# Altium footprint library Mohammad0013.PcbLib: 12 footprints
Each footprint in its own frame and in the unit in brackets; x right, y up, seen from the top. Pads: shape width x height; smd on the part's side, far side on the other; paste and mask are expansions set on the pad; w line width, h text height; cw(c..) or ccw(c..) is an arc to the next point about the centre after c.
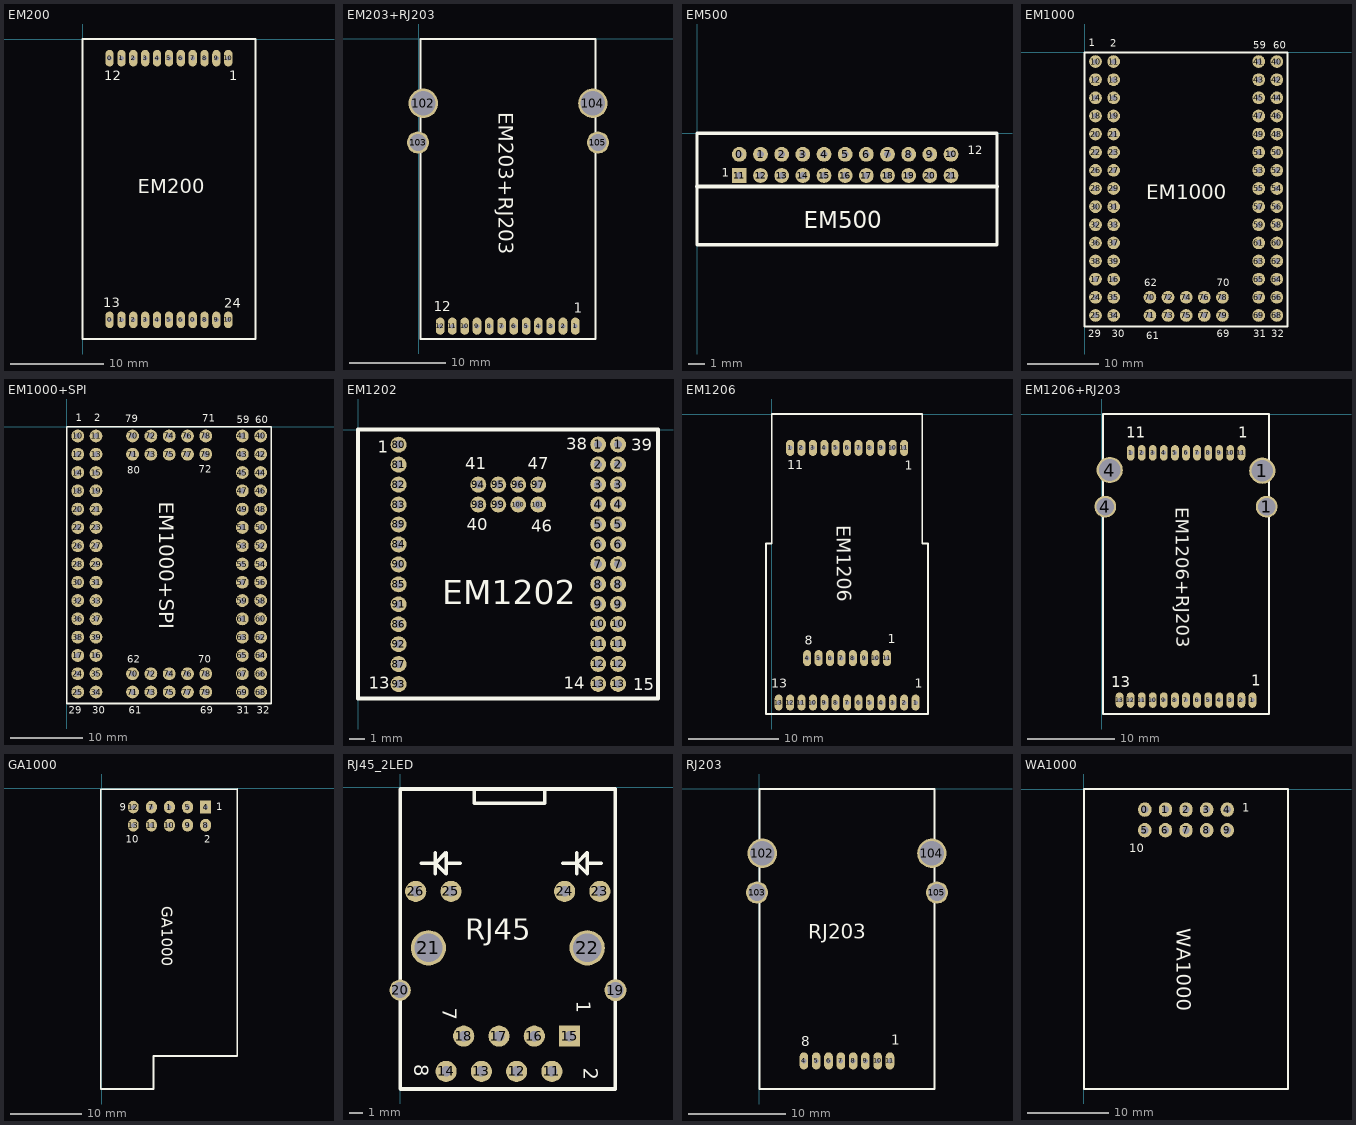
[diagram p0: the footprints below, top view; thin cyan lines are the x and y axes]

## EM200 [mil]
pads (22):
  oval 35x70 hole 20: 0(113.78,-1183.07) 0(113.78,-80.71) 0(463.78,-1183.07) 1(163.78,-1183.07) 1(163.78,-80.71) 2(213.78,-1183.07) 2(213.78,-80.71) 3(263.78,-1183.07) 3(263.78,-80.71) 4(313.78,-1183.07) 4(313.78,-80.71) 5(363.78,-1183.07) 5(363.78,-80.71) 6(413.78,-1183.07) 6(413.78,-80.71) 7(463.78,-80.71) 8(513.78,-1183.07) 8(513.78,-80.71) 9(563.78,-1183.07) 9(563.78,-80.71) 10(613.78,-1183.07) 10(613.78,-80.71)
Top Overlay:
  lines w10: 0,-1263.78 0,0 728.35,0 728.35,-1263.78 0,-1263.78
  text "24" at 596.46,-1132.87 h40
  text "13" at 86.61,-1129.92 h40
  text "1" at 618.11,-173.23 h40
  text "12" at 91.54,-173.23 h40
  text "EM200" at 232.28,-650.59 h60

## EM203+RJ203 [mm]
pads (16):
  oval 0.889x1.778 hole 0.5: 1(16.155,-29.725) 2(14.885,-29.725) 3(13.615,-29.725) 4(12.345,-29.725) 5(11.075,-29.725) 6(9.805,-29.725) 7(8.535,-29.725) 8(7.265,-29.725) 9(5.995,-29.725) 10(4.725,-29.725) 11(3.455,-29.725) 12(2.185,-29.725)
  round 3.048 hole 2.54: 102(0.45,-6.7) 104(17.975,-6.7)
  round 2.286 hole 1.778: 103(-0.1,-10.75) 105(18.5,-10.75)
Top Overlay:
  lines w0.203: 0.15,-31.05 0.15,-0.05 18.25,-0.05 18.25,-31.05 0.15,-31.05
  text "EM203+RJ203" at 8.225,-7.625 h1.52
  text "1" at 16,-28.325 h1.02
  text "12" at 1.525,-28.2 h1.02

## EM500 [mil]
pads (22):
  round 35 hole 16: 0(100,-50) 1(150,-50) 2(200,-50) 3(250,-50) 4(300,-50) 5(350,-50) 6(400,-50) 7(450,-50) 8(500,-50) 9(550,-50) 10(600,-50) 12(150,-100) 13(200,-100) 14(250,-100) 15(300,-100) 16(350,-100) 17(400,-100) 18(450,-100) 19(500,-100) 20(550,-100) 21(600,-100)
  rect 35x35 hole 16: 11(100,-100)
Top Overlay:
  lines w8: 0,-263.78 0,0 708.66,0 708.66,-263.78 0,-263.78
  lines w10: 0,-125.98 708.66,-125.98
  text "12" at 640,-50 h20
  text "1" at 59.06,-102.36 h20
  text "EM500" at 251.97,-224.41 h40

## EM1000 [mil]
pads (70):
  round 70 hole 30: 10(60,-50) 11(160,-50) 12(60,-150) 13(160,-150) 14(60,-250) 15(160,-250) 16(160,-1250) 17(60,-1250) 18(60,-350) 19(160,-350) 20(60,-450) 21(160,-450) 22(60,-550) 23(160,-550) 24(60,-1350) 25(60,-1450) 26(60,-650) 27(160,-650) 28(60,-750) 29(160,-750) 30(60,-850) 31(160,-850) 32(60,-950) 33(160,-950) 34(160,-1450) 35(160,-1350) 36(60,-1050) 37(160,-1050) 38(60,-1150) 39(160,-1150) 40(1060,-50) 41(960,-50) 42(1060,-150) 43(960,-150) 44(1060,-250) 45(960,-250) 46(1060,-350) 47(960,-350) 48(1060,-450) 49(960,-450) 50(1060,-550) 51(960,-550) 52(1060,-650) 53(960,-650) 54(1060,-750) 55(960,-750) 56(1060,-850) 57(960,-850) 58(1060,-950) 59(960,-950) 60(1060,-1050) 61(960,-1050) 62(1060,-1150) 63(960,-1150) 64(1060,-1250) 65(960,-1250) 66(1060,-1350) 67(960,-1350) 68(1060,-1450) 69(960,-1450) 70(360,-1350) 71(360,-1450) 72(460,-1350) 73(460,-1450) 74(560,-1350) 75(560,-1450) 76(660,-1350) 77(660,-1450) 78(760,-1350) 79(760,-1450)
Top Overlay:
  lines w10: 0,-1511.81 0,0 1118.11,0 1118.11,-1511.81 0,-1511.81
  text "EM1000" at 340,-810 h80
  text "1" at 22.64,34.45 h40
  text "2" at 140.75,31.5 h40
  text "29" at 20,-1570 h40
  text "30" at 150,-1570 h40
  text "62" at 330,-1290 h40
  text "61" at 340,-1580 h40
  text "70" at 730,-1290 h40
  text "69" at 730,-1570 h40
  text "31" at 930,-1570 h40
  text "32" at 1030,-1570 h40
  text "59" at 930,20 h40
  text "60" at 1040,20 h40

## EM1000+SPI [mil]
pads (80):
  round 70 hole 30: 10(60,-50) 11(160,-50) 12(60,-150) 13(160,-150) 14(60,-250) 15(160,-250) 16(160,-1250) 17(60,-1250) 18(60,-350) 19(160,-350) 20(60,-450) 21(160,-450) 22(60,-550) 23(160,-550) 24(60,-1350) 25(60,-1450) 26(60,-650) 27(160,-650) 28(60,-750) 29(160,-750) 30(60,-850) 31(160,-850) 32(60,-950) 33(160,-950) 34(160,-1450) 35(160,-1350) 36(60,-1050) 37(160,-1050) 38(60,-1150) 39(160,-1150) 40(1060,-50) 41(960,-50) 42(1060,-150) 43(960,-150) 44(1060,-250) 45(960,-250) 46(1060,-350) 47(960,-350) 48(1060,-450) 49(960,-450) 50(1060,-550) 51(960,-550) 52(1060,-650) 53(960,-650) 54(1060,-750) 55(960,-750) 56(1060,-850) 57(960,-850) 58(1060,-950) 59(960,-950) 60(1060,-1050) 61(960,-1050) 62(1060,-1150) 63(960,-1150) 64(1060,-1250) 65(960,-1250) 66(1060,-1350) 67(960,-1350) 68(1060,-1450) 69(960,-1450) 70(360,-1350) 70(360,-50) 71(360,-1450) 71(360,-150) 72(460,-1350) 72(460,-50) 73(460,-1450) 73(460,-150) 74(560,-1350) 74(560,-50) 75(560,-1450) 75(560,-150) 76(660,-1350) 76(660,-50) 77(660,-1450) 77(660,-150) 78(760,-1350) 78(760,-50) 79(760,-1450) 79(760,-150)
Top Overlay:
  lines w10: 0,-1511.81 1118.11,-1511.81 1118.11,0 0,0 0,-1511.81
  text "80" at 330,-256.89 h40
  text "79" at 321,23.62 h40
  text "72" at 722,-250.98 h40
  text "71" at 740,26.57 h40
  text "EM1000+SPI" at 506.89,-409.45 h80
  text "1" at 50,30 h40
  text "2" at 150,30 h40
  text "29" at 10,-1570 h40
  text "30" at 140,-1570 h40
  text "62" at 330,-1290 h40
  text "61" at 340,-1570 h40
  text "70" at 720,-1290 h40
  text "69" at 730,-1570 h40
  text "31" at 930,-1570 h40
  text "32" at 1040,-1570 h40
  text "59" at 930,20 h40
  text "60" at 1030,20 h40

## EM1202 [mil]
pads (47):
  round 40 hole 19.68: 1(602,-37) 1(652,-37) 2(602,-87) 2(652,-87) 3(602,-137) 3(652,-137) 4(602,-187) 4(652,-187) 5(652,-237) 6(602,-287) 6(652,-287) 7(602,-337) 7(652,-337) 8(602,-387) 8(652,-387) 9(602,-437) 9(652,-437) 10(602,-487) 10(652,-487) 11(602,-537) 11(652,-537) 12(602,-587) 12(652,-587) 13(602,-637) 13(652,-637)
  round 40 hole 20: 5(602,-237) 80(101.61,-37.55) 81(101.61,-87.55) 82(101.61,-137.55) 83(101.61,-187.55) 84(101.61,-287.55) 85(101.61,-387.55) 86(101.61,-487.55) 87(101.61,-587.55) 89(101.61,-237.55) 90(101.61,-337.55) 91(101.61,-437.55) 92(101.61,-537.55) 93(101.61,-637.55) 94(301.61,-137.55) 95(351.61,-137.55) 96(401.61,-137.55) 97(451.61,-137.55) 98(301.61,-187.55) 99(351.61,-187.55) 100(401.61,-187.55) 101(451.61,-187.55)
Top Overlay:
  lines w10: 0,-673.23 0,0 751.97,0 751.97,-673.23 0,-673.23
  text "46" at 434.06,-255.91 h30
  text "40" at 272.64,-251.97 h30
  text "47" at 425.2,-99.41 h30
  text "41" at 268.7,-99.41 h30
  text "39" at 685.04,-52.17 h30
  text "38" at 521.65,-50.2 h30
  text "15" at 689.96,-653.54 h30
  text "14" at 515.75,-649.61 h30
  text "13" at 26.57,-649.61 h30
  text "1" at 49.21,-58.07 h30
  text "EM1202" at 211.61,-437.55 h60

## EM1206 [mil]
pads (32):
  oval 35x70 hole 19.68: 1(80,-148.62) 1(630,-1264.76) 2(130,-148.62) 2(580,-1264.76) 3(180,-148.62) 3(530,-1264.76) 4(155,-1069.88) 4(230,-148.62) 4(480,-1264.76) 5(205,-1069.88) 5(280,-148.62) 5(430,-1264.76) 6(255,-1069.88) 6(330,-148.62) 6(380,-1264.76) 7(305,-1069.88) 7(330,-1264.76) 7(380,-148.62) 8(280,-1264.76) 8(355,-1069.88) 8(430,-148.62) 9(230,-1264.76) 9(405,-1069.88) 9(480,-148.62) 10(180,-1264.76) 10(455,-1069.88) 10(530,-148.62) 11(130,-1264.76) 11(505,-1069.88) 11(580,-148.62) 12(80,-1264.76) 13(30,-1264.76)
Top Overlay:
  lines w8: -26.06,-1314.96 685.04,-1314.96 685.04,-566.93 658.98,-566.93 658.98,0 0,0 0,-566.93 -26.06,-566.93 -26.06,-1314.96
  text "1" at 581.69,-245.08 h40
  text "11" at 67.91,-242.13 h40
  text "1" at 626.97,-1199.8 h40
  text "13" at -2.95,-1199.8 h40
  text "EM1206" at 284.45,-487.2 h60
  text "1" at 509,-1004.92 h40
  text "8" at 144,-1010.83 h40

## EM1206+RJ203 [mm]
pads (28):
  oval 0.889x1.778 hole 0.5: 1(3.302,-4.45) 1(17.27,-32.8) 2(4.572,-4.45) 2(16,-32.8) 3(5.842,-4.45) 3(14.73,-32.8) 4(7.112,-4.45) 4(13.46,-32.8) 5(8.382,-4.45) 5(12.19,-32.8) 6(9.652,-4.45) 6(10.92,-32.8) 7(9.65,-32.8) 7(10.922,-4.45) 8(8.38,-32.8) 8(12.192,-4.45) 9(7.11,-32.8) 9(13.462,-4.45) 10(5.84,-32.8) 10(14.732,-4.45) 11(4.57,-32.8) 11(16.002,-4.45) 12(3.3,-32.8) 13(2.03,-32.8)
  round 3 hole 2.5: 1(18.4,-6.5) 4(0.9,-6.425)
  round 2.5 hole 2: 1(18.9,-10.625) 4(0.4,-10.625)
Top Overlay:
  lines w0.203: 0.127,-34.4 0.127,-6.418 0.127,0 19.177,0 19.177,-34.4 0.127,-34.4
  text "EM1206+RJ203" at 8.45,-10.675 h1.52
  text "13" at 1.075,-31.35 h1.27
  text "1" at 17.15,-31.15 h1.27
  text "11" at 2.825,-2.75 h1.27
  text "1" at 15.65,-2.75 h1.27

## GA1000 [mil]
pads (10):
  oval 60x70 hole 25: 1(375,-103.43) 5(475,-103.43) 7(275,-103.43) 8(575,-203.43) 9(475,-203.43) 10(375,-203.43) 11(275,-203.43) 12(175,-103.43) 13(175,-203.43)
  rect 60x70 hole 25: 4(575,-103.43)
Top Overlay:
  lines w7.87: -5,-1663.43 -5,-3.43 750,-3.43
  lines w10: -5,-1663.43 287.4,-1663.43 287.4,-1480.32 750,-1480.32 750,-3.43
  text "2" at 568.9,-300.2 h40
  text "1" at 633.86,-122.05 h40
  text "GA1000" at 331.69,-653.54 h60
  text "10" at 132.87,-300.2 h40
  text "9" at 100.39,-125 h40

## RJ45_2LED [mil] "RJ45_2LED"
pads (16):
  round 60 hole 30: 11(430.24,-804.33) 12(330.24,-804.33) 13(230.24,-804.33) 14(130.24,-804.33) 16(380.24,-704.33) 17(280.24,-704.33) 18(180.24,-704.33) 23(566.24,-294.33) 24(466.24,-294.33) 25(144.24,-294.33) 26(44.24,-294.33)
  rect 60x60 hole 30: 15(480.24,-704.33)
  round 62 hole 45: 19(610.24,-574.33)
  round 60 hole 45: 20(0.24,-574.33)
  round 100 hole 80: 21(80.24,-454.33) 22(530.24,-454.33)
Top Overlay:
  lines w10: 60.24,-214.33 100.24,-214.33 ; 100.24,-184.33 100.24,-244.33 100.24,-214.33 ; 170.24,-214.33 130.24,-214.33 130.24,-244.33 ; 210.24,-4.33 210.24,-44.33 410.24,-44.33 410.24,-4.33 ; 460.24,-214.33 500.24,-214.33 ; 500.24,-244.33 500.24,-184.33 500.24,-214.33 ; 570.24,-214.33 530.24,-214.33 530.24,-244.33 ; 100.24,-214.33 130.24,-184.33 130.24,-244.33 ; 100.24,-214.33 130.24,-244.33 ; 500.24,-214.33 530.24,-244.33 ; 500.24,-214.33 530.24,-184.33 530.24,-244.33 ; 0.24,-853.33 1.24,-854.33 610.24,-854.33 610.24,-4.33 1.24,-4.33 0.24,-5.33 0.24,-853.33
  text "1" at 500.24,-604.33 h40
  text "2" at 520.24,-794.33 h40
  text "7" at 120.24,-624.33 h40
  text "8" at 40.24,-784.33 h40
  text "RJ45" at 185.04,-432.09 h60

## RJ203 [mm]
pads (12):
  oval 0.889x1.778 hole 0.5: 4(4.6,-28.125) 5(5.87,-28.125) 6(7.14,-28.125) 7(8.41,-28.125) 8(9.68,-28.125) 9(10.95,-28.125) 10(12.22,-28.125) 11(13.49,-28.125)
  round 3.048 hole 2.54: 102(0.3,-6.675) 104(17.825,-6.675)
  round 2.286 hole 1.778: 103(-0.25,-10.725) 105(18.35,-10.725)
Top Overlay:
  lines w0.203: 0,-31.025 18.1,-31.025 18.1,-0.025 0,-0.025 0,-31.025
  text "8" at 4.331,-26.625 h1.02
  text "1" at 13.602,-26.475 h1.02
  text "RJ203" at 5.025,-15.5 h1.52

## WA1000 [mil]
pads (10):
  oval 65x70 hole 35: 0(296.26,-100) 1(396.26,-100) 2(496.26,-100) 3(596.26,-100) 4(696.26,-100) 5(296.26,-200) 6(396.26,-200) 7(496.26,-200) 8(596.26,-200) 9(696.26,-200)
Top Overlay:
  lines w10: 0,-1456.69 992.13,-1456.69 992.13,0 0,0 0,-1456.69
  text "10" at 221.46,-307.09 h40
  text "1" at 768.7,-111.22 h40
  text "WA1000" at 450.79,-677.17 h70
